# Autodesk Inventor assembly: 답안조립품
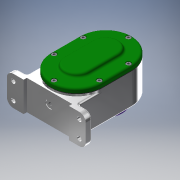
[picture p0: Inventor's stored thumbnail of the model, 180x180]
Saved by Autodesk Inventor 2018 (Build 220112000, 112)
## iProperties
Created: 2021-05
Part Number: 답안조립품
Material: 일반
Document SubType Name: Assembly
Designer: Admin
Author: Admin
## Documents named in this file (19)
- C:\Users\Admin\Desktop\710509V1015\공용부품\답안조립품.iam
- C:\Users\Admin\Desktop\710509V1015\본체.ipt
- C:\Users\Admin\Desktop\710509V1015\공용부품\축 A.ipt
- C:\Users\Admin\Desktop\710509V1015\공용부품\베어링 6001.ipt
- 베어링 6001.ipt
- C:\Users\Admin\Desktop\710509V1015\공용부품\베어링 6002.ipt
- 베어링 6002.ipt
- C:\Users\Admin\Desktop\710509V1015\공용부품\칼라.ipt
- C:\Users\Admin\Desktop\710509V1015\공용부품\키 5 x 5 x 12.ipt
- C:\Users\Admin\Desktop\710509V1015\공용부품\스퍼기어 A.ipt
- C:\Users\Admin\Desktop\710509V1015\공용부품\축 B.ipt
- C:\Users\Admin\Desktop\710509V1015\공용부품\키 4 x 4 x 12.ipt
- C:\Users\Admin\Desktop\710509V1015\공용부품\스퍼기어 B.ipt
- C:\Users\Admin\Desktop\710509V1015\공용부품\개스킷 A.ipt
- C:\Users\Admin\Desktop\710509V1015\공용부품\개스킷 B.ipt
- C:\Users\Admin\Desktop\710509V1015\공용부품\커버 A.ipt
- C:\Users\Admin\Desktop\710509V1015\공용부품\커버 B.ipt
- C:\Users\Admin\Desktop\710509V1015\공용부품\볼트 M4.ipt
- C:\Users\Admin\Desktop\710509V1015\공용부품\오일 실 12 22 7.ipt
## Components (2 placed, 2 different names)
1. 개스킷 A:1
2. 개스킷 B:1
